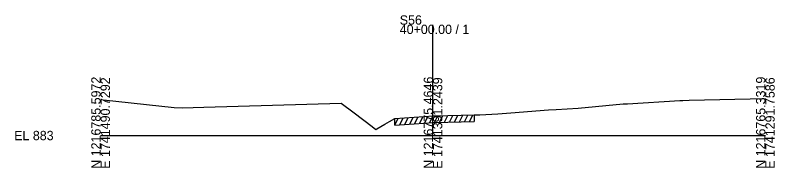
# Model space of a CAD drawing. Extents: x -26 to 1203, y -10 to 19541.
# Drawn here: x -25.7 to 202.8, y 14990.3 to 15036.2 of the extents above; entities that cross this region are included whole.
import ezdxf

# ---------------------------------------------------------------- set-up
doc = ezdxf.new("R2010")
doc.units = 0
for name, color, linetype in [('RD_GPK_XS_Cell', 7, 'Continuous'), ('RD_XS_ExGround', 7, 'Continuous'), ('RD_XS_ExPaveRet', 7, 'Continuous'), ('RD_XS_TX_Elev_EX', 7, 'Continuous')]:
    doc.layers.add(name, color=color, linetype=linetype)

msp = doc.modelspace()

# ---------------------------------------------------------------- linework, layer by layer
at = {"layer": 'RD_GPK_XS_Cell'}
for p, q in [((100, 15000), (100, 15033.31)), ((0, 15000), (100, 15000)), ((100, 15000), (200, 15000))]:
    msp.add_line(p, q, dxfattribs=at)
at = {"layer": 'RD_XS_ExGround'}
msp.add_lwpolyline([(0.88, 15010.7), (22.15, 15008.45), (24.68, 15008.35), (31.05, 15008.52), (72.35, 15009.74), (76.26, 15006.78), (81.7, 15002.68), (82.78, 15001.86), (83.08, 15002.03), (85.5, 15003.39), (86.92, 15004.23), (88.49, 15005.16), (100.2, 15005.91), (100.58, 15005.91), (112.43, 15006.19), (114.07, 15006.21), (115.9, 15006.36), (119.48, 15006.51), (123.47, 15006.8), (134.73, 15007.72), (137.07, 15007.87), (143.65, 15008.25), (157.23, 15009.51), (158.56, 15009.57), (174.27, 15010.52), (175.19, 15010.54), (177.05, 15010.63), (200, 15011.1)], dxfattribs=at)
at = {"layer": 'RD_XS_ExPaveRet'}
for p, q in [((92.99, 15003.45), (94.02, 15005.51)), ((94.49, 15003.54), (95.52, 15005.61)), ((95.99, 15003.64), (97.02, 15005.7)), ((97.49, 15003.73), (98.52, 15005.8)), ((98.99, 15003.83), (100.02, 15005.9)), ((100.49, 15003.91), (101.5, 15005.93)), ((101.99, 15003.94), (103, 15005.97)), ((103.49, 15003.98), (104.5, 15006)), ((104.99, 15004.01), (106, 15006.04)), ((106.49, 15004.05), (107.5, 15006.07)), ((107.99, 15004.08), (109, 15006.11)), ((109.49, 15004.12), (110.5, 15006.14)), ((110.99, 15004.15), (112, 15006.18)), ((112.43, 15006.19), (112.43, 15004.19)), ((88.49, 15003.16), (89.52, 15005.22)), ((88.49, 15003.16), (88.49, 15005.16)), ((88.49, 15003.16), (100.2, 15003.91)), ((89.99, 15003.25), (91.02, 15005.32)), ((91.49, 15003.35), (92.52, 15005.42)), ((100.2, 15003.91), (100.58, 15003.91)), ((100.58, 15003.91), (112.43, 15004.19))]:
    msp.add_line(p, q, dxfattribs=at)

# ---------------------------------------------------------------- texts
at = {"layer": 'RD_GPK_XS_Cell'}
for s, p in [('S56', (90, 15033.31)), ('40+00.00 / 1', (90, 15030.51)), ('EL 883', (-26, 14998.6))]:
    msp.add_text(s, height=2.8, dxfattribs=at).set_placement(p)
for s, p in [('N 1216785.5972', (0, 14990)), ('E 1741490.7292', (2.8, 14990)), ('N 1216775.4646', (100, 14990)), ('E 1741391.2439', (102.8, 14990)), ('N 1216765.3319', (200, 14990)), ('E 1741291.7586', (202.8, 14990))]:
    msp.add_text(s, height=2.8, rotation=90, dxfattribs=at).set_placement(p)
at = {"layer": 'RD_XS_TX_Elev_EX'}
msp.add_text('885.95', height=0.1, rotation=90, dxfattribs=at).set_placement((100.1, 15005.89))

doc.saveas('drawing.dxf')
